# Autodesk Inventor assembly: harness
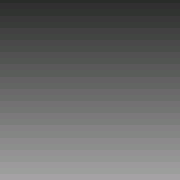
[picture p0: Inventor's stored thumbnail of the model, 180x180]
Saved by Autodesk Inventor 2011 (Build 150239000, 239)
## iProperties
HarnessSettings: <HarnessSettings><Defaults><Segments><Diameter value="0.200 in" fromwires="True"/><Offset value="0.100 in"/><ColorStyle value="Blue"/><BendRadius value="19" fro
Control State: 0
Master: False
Checked Out: False
Part Number: harness
Document SubType Name: Assembly
Created: 2002-07
Designer: invbi
Shininess: 64.0
Length Units: 11272
Angle Units: 11279
Time Units: 11290
Mass Units: 11286
Length Display Precision: 3
Angle Display Precision: 2
Compacted: True
Density: 0.0
Volumn: 0.0
Area: 0.0
PropertySet Name: Model Information
HarnessSettings: <HarnessSettings><Defaults><Segments><Diameter value="0.200 in" fromwires="True"/><Offset value="0.100 in"/><ColorStyle value="Bleu"/><RoundUp value=""/><BendRa
Author: invbi
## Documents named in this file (1)
- D:\Template\FRA\harness.iam
